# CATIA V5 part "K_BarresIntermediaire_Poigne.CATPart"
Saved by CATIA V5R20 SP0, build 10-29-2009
Part number: barres_intermediaire_poigne_volume
Bounding box of the stored display mesh (mm): x -76.886 to 74.988, y -125 to 125, z -24.988 to 1026.886
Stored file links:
  G:\Khaled_CFAO_2011\ST2M\ST2M_GR1\cdurantin\cdurantin\Khaled\CAD_ThinkMOTION\K_BarresIntermediaire_Poigne.CATPart
  C:\Documents and Settings\cdurantin\Bureau\cdurantin\caddy.CATProduct
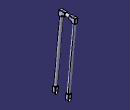
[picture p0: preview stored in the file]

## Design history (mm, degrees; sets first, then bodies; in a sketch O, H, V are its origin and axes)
External parameters (linked from other documents)
  `External.diamètre des barres` = 40 mm
  `External.Surepaisseur du tube` = 10 mm
  `External.ecart entre les barres` = 200 mm
  `External.hauteur des barres` = 1000 mm
Set1
  Line1: linked copy from another document
  Point1: linked copy from another document
  Line2 to Line4: linked copy from another document
Body1 "raccords du bas" (main body)
  Plane1: type Offset, RefPlane zx-plane, Offset 100 {= `External.ecart entre les barres` /2}, reversed
  Sketch1 on Plane1, origin (0, -100, 0), H (-1, 0, 0), V (0, 0, 1)
    circle A1 centre (-50, 0) radius 20
    reference projected point E2 (-50, 0) from Point1
    arc A2 centre (-50, 0) radius 25 from (-74.8759, 2.4876) to (-25.1241, -2.4876) ccw
    line L1 (-17.6613, 72.1402) -> (-25.1241, -2.4876)
    line L2 (-17.6613, 72.1402) -> (-67.4132, 77.1154)
    line L3 (-67.4132, 77.1154) -> (-74.8759, 2.4876)
    reference projected line E3 (30.2225, 802.2246) -> (-50, 0) from Line2
    radius A1 = 20 {= `External.diamètre des barres` /2}
    radius A2 = 25 {= (`External.diamètre des barres` +`External.Surepaisseur du tube` )/2}
    length L2 = 50 {= `External.diamètre des barres` +`External.Surepaisseur du tube`}
    distance E3 L1 = 25 {= (`External.diamètre des barres` +`External.Surepaisseur du tube` )/2}
    distance L2 A2 = 50 {= `External.diamètre des barres` +`External.Surepaisseur du tube`}
    concentricity: E2 A1, A1 A2
    perpendicularity: L2 L1
    parallelism: L3 L1
  Pad1: profile Sketch1, direction (0, 1, 0), length 25 {= (`External.diamètre des barres` +`External.Surepaisseur du tube` )/2}, mirrored extent
  Sketch2 on face of Pad1 from Sketch1.L2, origin (37.8855, -97.1767, 74.1626), H (0.995, 0, 0.0995), V (0, 1, 0)
    point P1 (4.6749, -2.8233)
    reference projected point E1 (4.6749, -2.8233) from Line2
    distance E1 P1 = 0
  Hole1: placed by Sketch2, at (42.5372, -100, 74.6278) direction (0.0995, 0, -0.995), diameter 40 {= `External.diamètre des barres`}, depth 50 {= `External.diamètre des barres` +`External.Surepaisseur du tube`}
  Fillet1: radius 5, on edge [face of Pad1 from Sketch1.L3 | face of Pad1 from Sketch1.L2]; edge [start face of Pad1 | face of Pad1 from Sketch1.L2]; edge [face of Pad1 from Sketch1.L2 | face of Pad1 from Sketch1.L1]; edge [face of Pad1 from Sketch1.L2 | end face of Pad1]; edge [face of Pad1 from Sketch1.L3 | end face of Pad1]; edge [start face of Pad1 | face of Pad1 from Sketch1.L3]
  Mirror1: of the body so far, about zx-plane
Body2 "barre montante"
  Sketch3 on Plane1, origin (0, -100, 0), H (-1, 0, 0), V (0, 0, 1)
    line L1 (50, 1000) -> (69.9007, 998.0099)
    line L2 (69.9007, 998.0099) -> (-25.1241, 47.7618)
    line L3 (-25.1241, 47.7618) -> (-45.0248, 49.7519)
    line L4 (-45.0248, 49.7519) -> (50, 1000)
    reference projected line E1 (30.2225, 802.2246) -> (-50, 0) from Line2
    reference projected point E2 (-50, 0) from Line1
    reference projected point E3 (50, 1000) from Line3
    distance L4 E1 = 0
    distance L3 E2 = 50 {= `External.diamètre des barres` +`External.Surepaisseur du tube`}
    distance E3 L1 = 0
    distance L4 L2 = 20 {= `External.diamètre des barres` /2}
    perpendicularity: L2 L1
    parallelism: L3 L1
  Shaft1: profile Sketch3, axis Line2, angle 360
  Mirror2: of the body so far, about zx-plane
Body3 "partie superieure"
  Plane2: type 2Lines, Element1 Line3, Element2 Line2
  Sketch4 on Plane2, origin (49.3829, 0, 6.171), H (0, 1, 0), V (-0.0995, 0, 0.995)
    line L1 (-125, 1023.7858) -> (-88.4512, 1023.7858)
    line L2 (-75, 973.7858) -> (-75, 948.7858)
    line L3 (-75, 948.7858) -> (-125, 948.7858)
    line L4 (-125, 948.7858) -> (-125, 1023.7858)
    point P2 (-88.4512, 1023.7858)
    point P5 (-88.4512, 1023.7858)
    line L5 (-88.4512, 1023.7858) -> (-30, 1023.7858)
    line L6 (-30, 1023.7858) -> (-30, 973.7858)
    line L7 (-30, 973.7858) -> (-75, 973.7858)
    reference projected line E1 (-100, 800.024) -> (-100, -6.2017) from Line2
    reference projected line E2 (100, 998.7858) -> (-100, 998.7858) from Line3
    reference projected line E3 (100, 998.7858) -> (-100, 998.7858) from Line3
    length L3 = 50 {= `External.diamètre des barres` +`External.Surepaisseur du tube`}
    distance E1 L2 = 25 {= (`External.diamètre des barres` +`External.Surepaisseur du tube` )/2}
    distance L3 E2 = 50 {= `External.diamètre des barres` +`External.Surepaisseur du tube`}
    distance L6 L2 = 45 {= `External.diamètre des barres` +`External.Surepaisseur du tube` /2}
    distance P5 P2 = 0
    distance L5 E3 = 25 {= (`External.diamètre des barres` +`External.Surepaisseur du tube` )/2}
    length L6 = 50 {= `External.diamètre des barres` +`External.Surepaisseur du tube`}
    horizontal: L1 H, L3 H, L5 H, L7 H
    vertical: L2 V, L4 V, L6 V
  Pad2: profile Sketch4, direction (0.995, 0, 0.0995), length 25 {= (`External.diamètre des barres` +`External.Surepaisseur du tube` )/2}, mirrored extent
  Sketch5 on face of Pad2 from Sketch4.L3, origin (-57.2346, -91.1478, 949.0272), H (0.995, 0, 0.0995), V (0, -1, 0)
    point P1 (12.2706, 8.8522)
    reference projected point E1 (12.2706, 8.8522) from Line2
    distance E1 P1 = 0
  Hole2: placed by Sketch5, at (-45.0248, -100, 950.2481) direction (-0.0995, 0, 0.995), diameter 40 {= `External.diamètre des barres`}, depth 50 {= `External.diamètre des barres` +`External.Surepaisseur du tube`}
  Sketch6 on face of Pad2 from Sketch4.L6, origin (-54.7979, -30, 809.0654), H (1, 0, 0), V (0, 0, -1)
    point P1 (4.7979, -190.9346)
    reference projected point E1 (4.7979, -190.9346) from Line3
    distance E1 P1 = 0
  Hole3: placed by Sketch6, at (-50, -30, 1000) direction (0, -1, 0), diameter 40 {= `External.diamètre des barres`}, depth 40 {= `External.diamètre des barres`}
  Fillet2: radius 5, on edge [face of Pad2 from Sketch4.L7 | end face of Pad2]; edge [face of Pad2 from Sketch4.L6 | end face of Pad2]; edge [face of Pad2 from Sketch4.L5 | face of Pad2 from Sketch4.L6]; edge [start face of Pad2 | face of Pad2 from Sketch4.L6]; edge [face of Pad2 from Sketch4.L6 | face of Pad2 from Sketch4.L7]; edge [face of Pad2 from Sketch4.L2 | end face of Pad2]; edge [face of Pad2 from Sketch4.L7 | face of Pad2 from Sketch4.L2]; edge [start face of Pad2 | face of Pad2 from Sketch4.L2]; edge [start face of Pad2 | face of Pad2 from Sketch4.L7]; edge [face of Pad2 from Sketch4.L2 | face of Pad2 from Sketch4.L3]; edge [face of Pad2 from Sketch4.L3 | end face of Pad2]; edge [face of Pad2 from Sketch4.L4 | end face of Pad2]; edge [face of Pad2 from Sketch4.L1 | end face of Pad2]; edge [face of Pad2 from Sketch4.L4 | face of Pad2 from Sketch4.L1]; edge [start face of Pad2 | face of Pad2 from Sketch4.L4]; edge [start face of Pad2 | face of Pad2 from Sketch4.L1]; edge [face of Pad2 from Sketch4.L3 | face of Pad2 from Sketch4.L4]; edge [start face of Pad2 | face of Pad2 from Sketch4.L3]
  Mirror3: of the body so far, about zx-plane
  Sketch7 on Plane2, origin (49.3829, 0, 6.171), H (0, 1, 0), V (-0.0995, 0, 0.995)
    line L1 (-60, 1018.7858) -> (60, 1018.7858)
    line L2 (60, 1018.7858) -> (60, 998.7858)
    line L3 (60, 998.7858) -> (-60, 998.7858)
    line L4 (-60, 998.7858) -> (-60, 1018.7858)
    reference projected line E1 (100, -6.2017) -> (100, 800.024) from Line4
    reference projected line E2 (-100, 800.024) -> (-100, -6.2017) from Line2
    reference projected line E3 (100, 998.7858) -> (-100, 998.7858) from Line3
    distance L2 E1 = 40 {= `External.diamètre des barres`}
    distance L4 E2 = 40 {= `External.diamètre des barres`}
    distance L3 E3 = 0
    length L2 = 20 {= `External.diamètre des barres` /2}
    horizontal: L1 H, L3 H
    vertical: L2 V, L4 V
  Shaft2: profile Sketch7, axis Line3, angle 360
